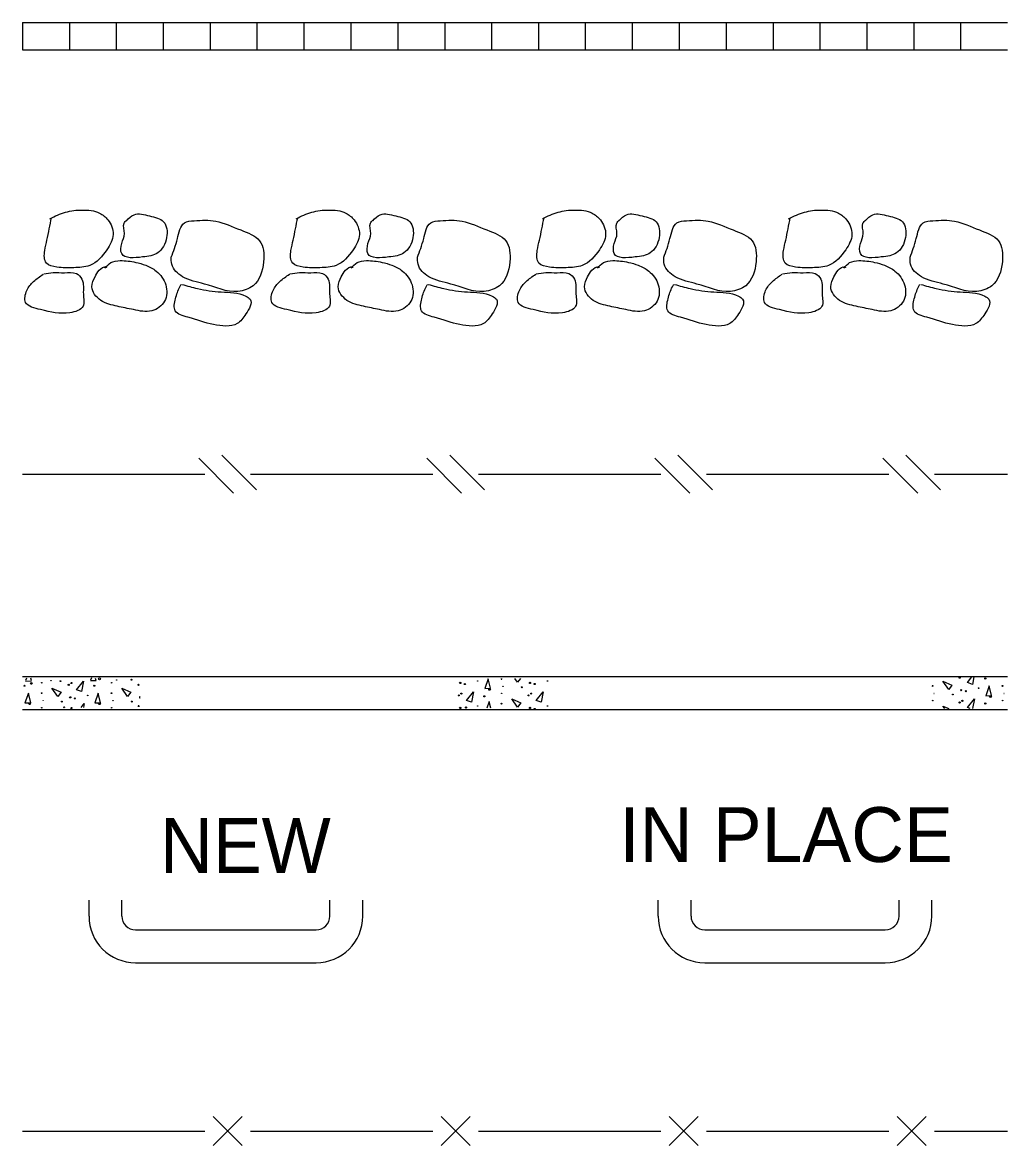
# Model space of a CAD drawing. Extents: x 49991.4 to 50021, y 49987.6 to 50011.4.
# Drawn here: x 50003.971 to 50005.051, y 49990.759 to 49991.99 of the extents above; entities that cross this region are included whole.
import ezdxf

# ---------------------------------------------------------------- set-up
doc = ezdxf.new("R2010")
doc.units = 0
doc.layers.add('Level 1', color=7, linetype='Continuous')
doc.layers.add('Level 2', color=7, linetype='Continuous')

msp = doc.modelspace()

# ---------------------------------------------------------------- linework, layer by layer
at = {"layer": 'Level 1'}
for p, q in [((50003.9708, 49991.9903), (50003.9708, 49991.9603)), ((50003.9708, 49991.9903), (50005.0508, 49991.9903)), ((50004.0222, 49991.9903), (50004.0222, 49991.9603)), ((50004.0737, 49991.9903), (50004.0737, 49991.9603)), ((50004.1251, 49991.9903), (50004.1251, 49991.9603)), ((50004.1765, 49991.9903), (50004.1765, 49991.9603)), ((50004.2279, 49991.9903), (50004.2279, 49991.9603)), ((50004.2794, 49991.9903), (50004.2794, 49991.9603)), ((50004.3308, 49991.9903), (50004.3308, 49991.9603)), ((50004.3308, 49991.9903), (50004.3308, 49991.9603)), ((50004.3822, 49991.9903), (50004.3822, 49991.9603)), ((50004.4337, 49991.9903), (50004.4337, 49991.9603)), ((50004.4851, 49991.9903), (50004.4851, 49991.9603)), ((50004.5365, 49991.9903), (50004.5365, 49991.9603)), ((50004.5879, 49991.9903), (50004.5879, 49991.9603)), ((50004.6394, 49991.9903), (50004.6394, 49991.9603)), ((50004.6908, 49991.9903), (50004.6908, 49991.9603)), ((50004.6908, 49991.9903), (50004.6908, 49991.9603)), ((50004.7422, 49991.9903), (50004.7422, 49991.9603)), ((50004.7937, 49991.9903), (50004.7937, 49991.9603)), ((50004.8451, 49991.9903), (50004.8451, 49991.9603)), ((50004.8965, 49991.9903), (50004.8965, 49991.9603)), ((50004.9479, 49991.9903), (50004.9479, 49991.9603)), ((50004.9994, 49991.9903), (50004.9994, 49991.9603)), ((50003.9708, 49991.9603), (50005.0508, 49991.9603)), ((50004.2023, 49991.4745), (50004.1642, 49991.5126)), ((50004.2274, 49991.4779), (50004.1893, 49991.516)), ((50004.4523, 49991.4745), (50004.4142, 49991.5126)), ((50004.4774, 49991.4779), (50004.4393, 49991.516)), ((50004.7023, 49991.4745), (50004.6642, 49991.5126)), ((50004.7274, 49991.4779), (50004.6893, 49991.516)), ((50004.9523, 49991.4745), (50004.9142, 49991.5126)), ((50004.9774, 49991.4779), (50004.9393, 49991.516)), ((50003.9708, 49991.4953), (50004.1708, 49991.4953)), ((50004.2208, 49991.4953), (50004.4208, 49991.4953)), ((50004.4708, 49991.4953), (50004.6708, 49991.4953)), ((50004.7208, 49991.4953), (50004.9208, 49991.4953)), ((50004.9708, 49991.4953), (50005.0508, 49991.4953)), ((50003.9708, 49991.2733), (50005.0508, 49991.2733)), ((50003.9752, 49991.2717), (50003.9743, 49991.2691)), ((50003.9743, 49991.2685), (50003.9807, 49991.2686)), ((50003.9806, 49991.2692), (50003.98, 49991.2717)), ((50004.03, 49991.2589), (50004.0376, 49991.2683)), ((50004.0376, 49991.2683), (50004.0354, 49991.2569)), ((50004.0453, 49991.2689), (50004.0517, 49991.269)), ((50004.0464, 49991.2719), (50004.0455, 49991.2693)), ((50004.0515, 49991.2689), (50004.0509, 49991.2714)), ((50004.4815, 49991.271), (50004.4776, 49991.2603)), ((50004.4841, 49991.2605), (50004.4815, 49991.271)), ((50004.5137, 49991.2672), (50004.5108, 49991.2713)), ((50004.5168, 49991.2713), (50004.5137, 49991.2672)), ((50004.9863, 49991.2593), (50004.9799, 49991.2684)), ((50004.9799, 49991.2684), (50004.9899, 49991.2641)), ((50004.9899, 49991.2641), (50004.9863, 49991.2593)), ((50005.0068, 49991.2668), (50005.0118, 49991.2729)), ((50005.0122, 49991.2648), (50005.0068, 49991.2668)), ((50005.0138, 49991.2729), (50005.0122, 49991.2648)), ((50005.0307, 49991.2632), (50005.0269, 49991.2524)), ((50005.0333, 49991.2526), (50005.0307, 49991.2632)), ((50005.0507, 49991.2733), (50005.0508, 49991.2733)), ((50003.9774, 49991.2553), (50003.9735, 49991.2446)), ((50003.9799, 49991.2447), (50003.9774, 49991.2553)), ((50004.0095, 49991.2514), (50004.0031, 49991.2605)), ((50004.0031, 49991.2605), (50004.0131, 49991.2562)), ((50004.0131, 49991.2562), (50004.0095, 49991.2514)), ((50004.0354, 49991.2569), (50004.03, 49991.2589)), ((50004.0539, 49991.2553), (50004.0501, 49991.2446)), ((50004.0565, 49991.2447), (50004.0539, 49991.2553)), ((50004.0861, 49991.2514), (50004.0797, 49991.2605)), ((50004.0797, 49991.2605), (50004.0897, 49991.2562)), ((50004.0897, 49991.2562), (50004.0861, 49991.2514)), ((50004.4576, 49991.2473), (50004.4652, 49991.2567)), ((50004.4652, 49991.2567), (50004.463, 49991.2453)), ((50004.4776, 49991.2603), (50004.4841, 49991.2605)), ((50004.5341, 49991.2473), (50004.5417, 49991.2567)), ((50004.5417, 49991.2567), (50004.5395, 49991.2453)), ((50005.0269, 49991.2524), (50005.0333, 49991.2526)), ((50003.9735, 49991.2446), (50003.9799, 49991.2447)), ((50004.0352, 49991.2395), (50004.0386, 49991.2437)), ((50004.0386, 49991.2437), (50004.0378, 49991.2395)), ((50004.0501, 49991.2446), (50004.0565, 49991.2447)), ((50004.463, 49991.2453), (50004.4576, 49991.2473)), ((50004.4825, 49991.2459), (50004.48, 49991.2389)), ((50004.4842, 49991.2386), (50004.4825, 49991.2456)), ((50004.5137, 49991.2398), (50004.5073, 49991.2489)), ((50004.5073, 49991.2489), (50004.5173, 49991.2446)), ((50004.5173, 49991.2446), (50004.5137, 49991.2398)), ((50004.5395, 49991.2453), (50004.5341, 49991.2473)), ((50004.9819, 49991.2383), (50004.9799, 49991.241)), ((50004.9799, 49991.241), (50004.9864, 49991.2383)), ((50005.0068, 49991.2394), (50005.0144, 49991.2488)), ((50005.01, 49991.2383), (50005.0068, 49991.2394)), ((50005.0144, 49991.2488), (50005.0123, 49991.2383)), ((50003.9708, 49991.2373), (50005.0508, 49991.2373)), ((50005.0507, 49991.2373), (50005.0508, 49991.2373)), ((50004.0438, 49991.0107), (50004.0438, 49991.0283)), ((50004.0798, 49991.0107), (50004.0798, 49991.0283)), ((50004.3078, 49991.0107), (50004.3078, 49991.0283)), ((50004.3438, 49991.0107), (50004.3438, 49991.0283)), ((50004.6678, 49991.0107), (50004.6678, 49991.0283)), ((50004.7038, 49991.0107), (50004.7038, 49991.0283)), ((50004.9318, 49991.0107), (50004.9318, 49991.0283)), ((50004.9678, 49991.0107), (50004.9678, 49991.0283)), ((50004.0948, 49990.9957), (50004.2928, 49990.9957)), ((50004.7188, 49990.9957), (50004.9168, 49990.9957)), ((50004.0948, 49990.9597), (50004.2928, 49990.9597)), ((50004.7188, 49990.9597), (50004.9168, 49990.9597)), ((50004.2117, 49990.7594), (50004.1799, 49990.7911)), ((50004.2117, 49990.7911), (50004.1799, 49990.7594)), ((50004.4617, 49990.7594), (50004.4299, 49990.7911)), ((50004.4617, 49990.7911), (50004.4299, 49990.7594)), ((50004.7117, 49990.7594), (50004.6799, 49990.7911)), ((50004.7117, 49990.7911), (50004.6799, 49990.7594)), ((50004.9617, 49990.7594), (50004.9299, 49990.7911)), ((50004.9617, 49990.7911), (50004.9299, 49990.7594)), ((50003.9708, 49990.7753), (50004.1708, 49990.7753)), ((50004.2208, 49990.7753), (50004.4208, 49990.7753)), ((50004.4708, 49990.7753), (50004.6708, 49990.7753)), ((50004.7208, 49990.7753), (50004.9208, 49990.7753)), ((50004.9708, 49990.7753), (50005.0508, 49990.7753))]:
    msp.add_line(p, q, dxfattribs=at)
for centre, radius in [((50003.973, 49991.2633), 0.000617), ((50003.9805, 49991.2658), 0.000949), ((50003.992, 49991.2666), 0.000294), ((50004.002, 49991.2689), 0.00015), ((50004.0124, 49991.2683), 0.000474), ((50004.0215, 49991.2643), 0.0006), ((50004.0245, 49991.2663), 0.000618), ((50004.0496, 49991.2633), 0.000617), ((50004.0553, 49991.2709), 0.000949), ((50004.0686, 49991.2666), 0.000294), ((50004.0741, 49991.2695), 0.00015), ((50004.0904, 49991.2699), 0.000474), ((50004.0981, 49991.2643), 0.0006), ((50004.4508, 49991.2664), 0.000665), ((50004.4558, 49991.2652), 0.000613), ((50004.4699, 49991.2685), 0.000327), ((50004.4977, 49991.2626), 0.00015), ((50004.5182, 49991.2616), 0.000474), ((50004.5273, 49991.2664), 0.000665), ((50004.5323, 49991.2652), 0.000613), ((50004.5464, 49991.2685), 0.000327), ((50004.9687, 49991.2631), 0.00045), ((50004.9983, 49991.2722), 0.0006), ((50005.0264, 49991.2712), 0.000617), ((50005.0452, 49991.2631), 0.00045), ((50003.9919, 49991.2552), 0.00045), ((50004.0232, 49991.2506), 0.000665), ((50004.0282, 49991.2494), 0.000613), ((50004.0423, 49991.2527), 0.000327), ((50004.0684, 49991.2552), 0.00045), ((50004.4491, 49991.2527), 0.0006), ((50004.452, 49991.2547), 0.000618), ((50004.4772, 49991.2517), 0.000617), ((50004.4829, 49991.2593), 0.000949), ((50004.4962, 49991.255), 0.000294), ((50004.5257, 49991.2527), 0.0006), ((50004.5286, 49991.2547), 0.000618), ((50004.9703, 49991.2548), 0.00015), ((50004.9908, 49991.2537), 0.000474), ((50005, 49991.2585), 0.000665), ((50005.005, 49991.2573), 0.000613), ((50005.0191, 49991.2606), 0.000327), ((50005.0321, 49991.2514), 0.000949), ((50005.0469, 49991.2548), 0.00015), ((50003.9787, 49991.2436), 0.000949), ((50003.992, 49991.2392), 0.000294), ((50003.9935, 49991.2469), 0.00015), ((50004.014, 49991.2459), 0.000474), ((50004.0245, 49991.2389), 0.000618), ((50004.0553, 49991.2436), 0.000949), ((50004.0686, 49991.2392), 0.000294), ((50004.0701, 49991.2469), 0.00015), ((50004.0906, 49991.2459), 0.000474), ((50004.4508, 49991.239), 0.000665), ((50004.4571, 49991.2394), 0.000613), ((50004.4699, 49991.2411), 0.000327), ((50004.496, 49991.2437), 0.00045), ((50004.5273, 49991.239), 0.000665), ((50004.5323, 49991.2378), 0.000613), ((50004.5464, 49991.2411), 0.000327), ((50004.9688, 49991.2471), 0.000294), ((50004.9983, 49991.2449), 0.0006), ((50005.0013, 49991.2468), 0.000618), ((50005.0264, 49991.2438), 0.000617), ((50005.0454, 49991.2471), 0.000294)]:
    msp.add_circle(centre, radius, dxfattribs=at)
for centre, radius, start, end in [((50004.496, 49991.271), 0.00045, 140.2072, 39.7928), ((50004.0997, 49991.2506), 0.000665, 91.0327, 268.9673), ((50004.0165, 49991.2393), 0.0006, 323.1308, 216.8692), ((50004.0981, 49991.2407), 0.0006, 323.1308, 216.8692), ((50004.0948, 49991.0107), 0.051, 180, 270), ((50004.0948, 49991.0107), 0.015, 180, 270), ((50004.2928, 49991.0107), 0.015, 270, 360), ((50004.2928, 49991.0107), 0.051, 270, 360), ((50004.7188, 49991.0107), 0.051, 180, 270), ((50004.7188, 49991.0107), 0.015, 180, 270), ((50004.9168, 49991.0107), 0.015, 270, 360), ((50004.9168, 49991.0107), 0.051, 270, 360)]:
    msp.add_arc(centre, radius, start, end, dxfattribs=at)
for points in [[(50004.0008, 49991.7751), (50004.0181, 49991.7823), (50004.0363, 49991.7847), (50004.0554, 49991.7813), (50004.0644, 49991.7739), (50004.0702, 49991.7579), (50004.0634, 49991.7412), (50004.0446, 49991.7239), (50004.027, 49991.7215), (50004.0085, 49991.7221), (50003.9971, 49991.7264), (50003.9952, 49991.7403), (50003.9977, 49991.7517), (50004.0002, 49991.7641), (50004.0026, 49991.7761)], [(50004.0848, 49991.773), (50004.0931, 49991.7795), (50004.1101, 49991.7782), (50004.1255, 49991.7718), (50004.1289, 49991.7545), (50004.1191, 49991.7378), (50004.1024, 49991.7332), (50004.0796, 49991.7369), (50004.0796, 49991.748), (50004.0826, 49991.7588), (50004.0823, 49991.7702), (50004.0851, 49991.7736)], [(50004.2708, 49991.7751), (50004.2881, 49991.7823), (50004.3063, 49991.7847), (50004.3254, 49991.7813), (50004.3344, 49991.7739), (50004.3402, 49991.7579), (50004.3334, 49991.7412), (50004.3146, 49991.7239), (50004.297, 49991.7215), (50004.2785, 49991.7221), (50004.2671, 49991.7264), (50004.2652, 49991.7403), (50004.2677, 49991.7517), (50004.2702, 49991.7641), (50004.2726, 49991.7761)], [(50004.3548, 49991.773), (50004.3631, 49991.7795), (50004.3801, 49991.7782), (50004.3955, 49991.7718), (50004.3989, 49991.7545), (50004.3891, 49991.7378), (50004.3724, 49991.7332), (50004.3496, 49991.7369), (50004.3496, 49991.748), (50004.3526, 49991.7588), (50004.3523, 49991.7702), (50004.3551, 49991.7736)], [(50004.5408, 49991.7751), (50004.5581, 49991.7823), (50004.5763, 49991.7847), (50004.5954, 49991.7813), (50004.6044, 49991.7739), (50004.6102, 49991.7579), (50004.6034, 49991.7412), (50004.5846, 49991.7239), (50004.567, 49991.7215), (50004.5485, 49991.7221), (50004.5371, 49991.7264), (50004.5352, 49991.7403), (50004.5377, 49991.7517), (50004.5402, 49991.7641), (50004.5426, 49991.7761)], [(50004.6248, 49991.773), (50004.6331, 49991.7795), (50004.6501, 49991.7782), (50004.6655, 49991.7718), (50004.6689, 49991.7545), (50004.6591, 49991.7378), (50004.6424, 49991.7332), (50004.6196, 49991.7369), (50004.6196, 49991.748), (50004.6226, 49991.7588), (50004.6223, 49991.7702), (50004.6251, 49991.7736)], [(50004.8108, 49991.7751), (50004.8281, 49991.7823), (50004.8463, 49991.7847), (50004.8654, 49991.7813), (50004.8744, 49991.7739), (50004.8802, 49991.7579), (50004.8734, 49991.7412), (50004.8546, 49991.7239), (50004.837, 49991.7215), (50004.8185, 49991.7221), (50004.8071, 49991.7264), (50004.8052, 49991.7403), (50004.8077, 49991.7517), (50004.8102, 49991.7641), (50004.8126, 49991.7761)], [(50004.8948, 49991.773), (50004.9031, 49991.7795), (50004.9201, 49991.7782), (50004.9355, 49991.7718), (50004.9389, 49991.7545), (50004.9291, 49991.7378), (50004.9124, 49991.7332), (50004.8896, 49991.7369), (50004.8896, 49991.748), (50004.8926, 49991.7588), (50004.8923, 49991.7702), (50004.8951, 49991.7736)], [(50004.1339, 49991.7329), (50004.1407, 49991.7533), (50004.1484, 49991.7705), (50004.1589, 49991.773), (50004.1827, 49991.7724), (50004.2101, 49991.7628), (50004.2308, 49991.7511), (50004.2351, 49991.7279), (50004.2237, 49991.7017), (50004.2071, 49991.6955), (50004.1703, 49991.7036), (50004.1463, 49991.7116), (50004.1345, 49991.7252), (50004.1339, 49991.7335)], [(50004.4039, 49991.7329), (50004.4107, 49991.7533), (50004.4184, 49991.7705), (50004.4289, 49991.773), (50004.4527, 49991.7724), (50004.4801, 49991.7628), (50004.5008, 49991.7511), (50004.5051, 49991.7279), (50004.4937, 49991.7017), (50004.4771, 49991.6955), (50004.4403, 49991.7036), (50004.4163, 49991.7116), (50004.4045, 49991.7252), (50004.4039, 49991.7335)], [(50004.6739, 49991.7329), (50004.6807, 49991.7533), (50004.6884, 49991.7705), (50004.6989, 49991.773), (50004.7227, 49991.7724), (50004.7501, 49991.7628), (50004.7708, 49991.7511), (50004.7751, 49991.7279), (50004.7637, 49991.7017), (50004.7471, 49991.6955), (50004.7103, 49991.7036), (50004.6863, 49991.7116), (50004.6745, 49991.7252), (50004.6739, 49991.7335)], [(50004.9439, 49991.7329), (50004.9507, 49991.7533), (50004.9584, 49991.7705), (50004.9689, 49991.773), (50004.9927, 49991.7724), (50005.0201, 49991.7628), (50005.0408, 49991.7511), (50005.0451, 49991.7279), (50005.0337, 49991.7017), (50005.0171, 49991.6955), (50004.9803, 49991.7036), (50004.9563, 49991.7116), (50004.9445, 49991.7252), (50004.9439, 49991.7335)], [(50004.0612, 49991.7211), (50004.0677, 49991.727), (50004.0779, 49991.7292), (50004.0951, 49991.7273), (50004.1059, 49991.7242), (50004.1174, 49991.7178), (50004.1279, 49991.7026), (50004.1266, 49991.6847), (50004.1127, 49991.6742), (50004.0924, 49991.6755), (50004.0748, 49991.6792), (50004.0566, 49991.6857), (50004.047, 49991.7005), (50004.0504, 49991.7116), (50004.055, 49991.7187), (50004.0627, 49991.7221), (50004.0633, 49991.7218)], [(50004.3312, 49991.7211), (50004.3377, 49991.727), (50004.3479, 49991.7292), (50004.3651, 49991.7273), (50004.3759, 49991.7242), (50004.3874, 49991.7178), (50004.3979, 49991.7026), (50004.3966, 49991.6847), (50004.3827, 49991.6742), (50004.3624, 49991.6755), (50004.3448, 49991.6792), (50004.3266, 49991.6857), (50004.317, 49991.7005), (50004.3204, 49991.7116), (50004.325, 49991.7187), (50004.3327, 49991.7221), (50004.3333, 49991.7218)], [(50004.6012, 49991.7211), (50004.6077, 49991.727), (50004.6179, 49991.7292), (50004.6351, 49991.7273), (50004.6459, 49991.7242), (50004.6574, 49991.7178), (50004.6679, 49991.7026), (50004.6666, 49991.6847), (50004.6527, 49991.6742), (50004.6324, 49991.6755), (50004.6148, 49991.6792), (50004.5966, 49991.6857), (50004.587, 49991.7005), (50004.5904, 49991.7116), (50004.595, 49991.7187), (50004.6027, 49991.7221), (50004.6033, 49991.7218)], [(50004.8712, 49991.7211), (50004.8777, 49991.727), (50004.8879, 49991.7292), (50004.9051, 49991.7273), (50004.9159, 49991.7242), (50004.9274, 49991.7178), (50004.9379, 49991.7026), (50004.9366, 49991.6847), (50004.9227, 49991.6742), (50004.9024, 49991.6755), (50004.8848, 49991.6792), (50004.8666, 49991.6857), (50004.857, 49991.7005), (50004.8604, 49991.7116), (50004.865, 49991.7187), (50004.8727, 49991.7221), (50004.8733, 49991.7218)], [(50003.9941, 49991.7147), (50004.0046, 49991.7162), (50004.0169, 49991.7159), (50004.0299, 49991.715), (50004.036, 49991.7088), (50004.0376, 49991.6924), (50004.0373, 49991.6792), (50004.0228, 49991.6721), (50003.9907, 49991.6755), (50003.9743, 49991.6835), (50003.9756, 49991.6965), (50003.983, 49991.7063), (50003.9935, 49991.7144)], [(50004.2641, 49991.7147), (50004.2746, 49991.7162), (50004.2869, 49991.7159), (50004.2999, 49991.715), (50004.306, 49991.7088), (50004.3076, 49991.6924), (50004.3073, 49991.6792), (50004.2928, 49991.6721), (50004.2607, 49991.6755), (50004.2443, 49991.6835), (50004.2456, 49991.6965), (50004.253, 49991.7063), (50004.2635, 49991.7144)], [(50004.5341, 49991.7147), (50004.5446, 49991.7162), (50004.5569, 49991.7159), (50004.5699, 49991.715), (50004.576, 49991.7088), (50004.5776, 49991.6924), (50004.5773, 49991.6792), (50004.5628, 49991.6721), (50004.5307, 49991.6755), (50004.5143, 49991.6835), (50004.5156, 49991.6965), (50004.523, 49991.7063), (50004.5335, 49991.7144)], [(50004.8041, 49991.7147), (50004.8146, 49991.7162), (50004.8269, 49991.7159), (50004.8399, 49991.715), (50004.846, 49991.7088), (50004.8476, 49991.6924), (50004.8473, 49991.6792), (50004.8328, 49991.6721), (50004.8007, 49991.6755), (50004.7843, 49991.6835), (50004.7856, 49991.6965), (50004.793, 49991.7063), (50004.8035, 49991.7144)], [(50004.1457, 49991.7032), (50004.1627, 49991.6986), (50004.1887, 49991.6949), (50004.2158, 49991.6903), (50004.2204, 49991.6869), (50004.2158, 49991.6708), (50004.2062, 49991.6603), (50004.1803, 49991.6591), (50004.1522, 49991.6671), (50004.1383, 49991.6742), (50004.1386, 49991.6875), (50004.1433, 49991.7005), (50004.1448, 49991.7032)], [(50004.4157, 49991.7032), (50004.4327, 49991.6986), (50004.4587, 49991.6949), (50004.4858, 49991.6903), (50004.4904, 49991.6869), (50004.4858, 49991.6708), (50004.4762, 49991.6603), (50004.4503, 49991.6591), (50004.4222, 49991.6671), (50004.4083, 49991.6742), (50004.4086, 49991.6875), (50004.4133, 49991.7005), (50004.4148, 49991.7032)], [(50004.6857, 49991.7032), (50004.7027, 49991.6986), (50004.7287, 49991.6949), (50004.7558, 49991.6903), (50004.7604, 49991.6869), (50004.7558, 49991.6708), (50004.7462, 49991.6603), (50004.7203, 49991.6591), (50004.6922, 49991.6671), (50004.6783, 49991.6742), (50004.6786, 49991.6875), (50004.6833, 49991.7005), (50004.6848, 49991.7032)], [(50004.9557, 49991.7032), (50004.9727, 49991.6986), (50004.9987, 49991.6949), (50005.0258, 49991.6903), (50005.0304, 49991.6869), (50005.0258, 49991.6708), (50005.0162, 49991.6603), (50004.9903, 49991.6591), (50004.9622, 49991.6671), (50004.9483, 49991.6742), (50004.9486, 49991.6875), (50004.9533, 49991.7005), (50004.9548, 49991.7032)]]:
    msp.add_spline(points, degree=3, dxfattribs=at)

# ---------------------------------------------------------------- texts
at = {"layer": 'Level 2'}
for s, p in [('IN PLACE', (50004.6252, 49991.0702)), ('NEW', (50004.1216, 49991.0582))]:
    msp.add_text(s, height=0.06, dxfattribs=at).set_placement(p)

doc.saveas('drawing.dxf')
